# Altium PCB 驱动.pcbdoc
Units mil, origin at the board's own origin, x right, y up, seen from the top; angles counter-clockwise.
Board outline 18951.26 x 3455 mil, 2 copper layers (Top Layer, Bottom Layer); 74 components, 198 nets, 542 pads, 63 vias.
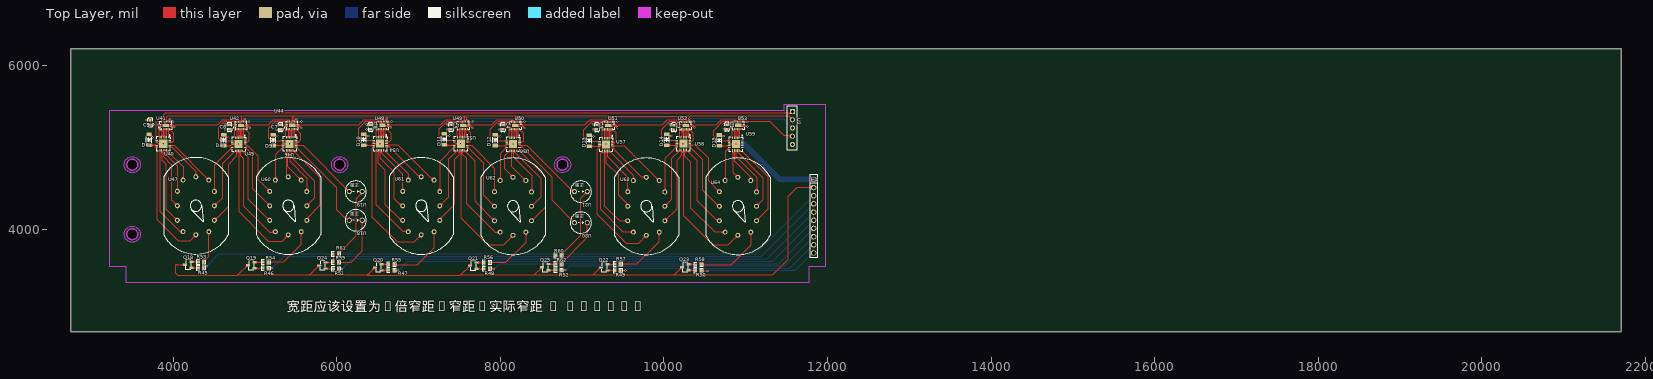
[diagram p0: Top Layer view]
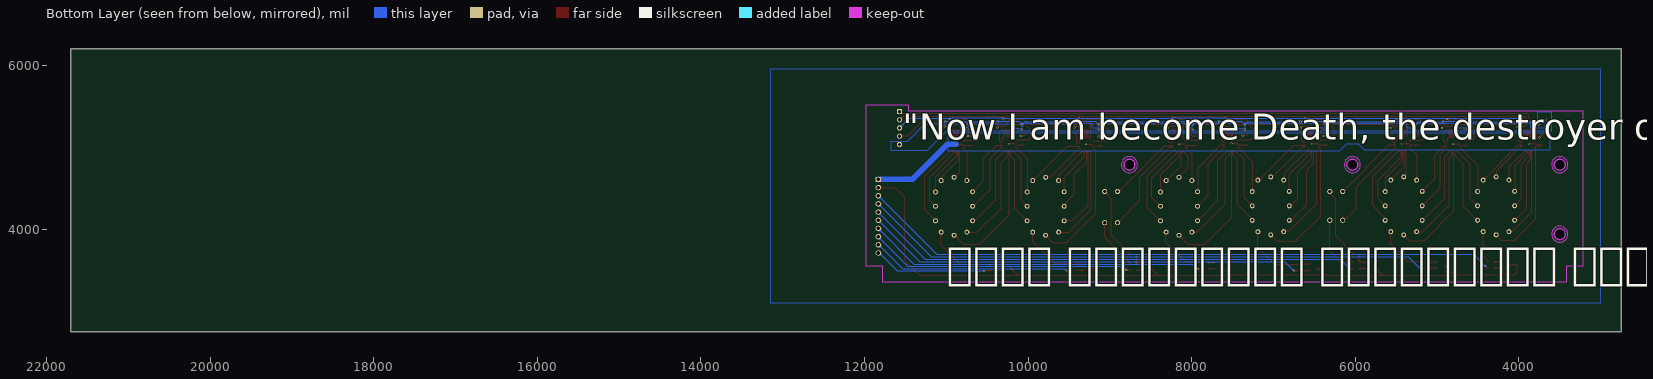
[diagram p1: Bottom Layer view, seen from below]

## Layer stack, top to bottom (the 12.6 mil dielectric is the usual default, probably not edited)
Top Layer: signal copper (thickness not stored)
Dielectric: dielectric 12.6, FR-4, Dk 4.8
Bottom Layer: signal copper (thickness not stored)

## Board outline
21701.26,2750 2750,2750 2750,6205 21701.26,6205
cut-out: 6101.93,4790 cw(c6035,4790) 5968.07,4790 cw(c6035,4790)
cut-out: 8826.93,4790 cw(c8760,4790) 8693.07,4790 cw(c8760,4790)
cut-out: 3566.93,3940 cw(c3500,3940) 3433.07,3940 cw(c3500,3940)
cut-out: 3566.93,4790 cw(c3500,4790) 3433.07,4790 cw(c3500,4790)

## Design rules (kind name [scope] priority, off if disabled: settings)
BoardOutlineClearance copperThickness1oz [All] p0: genericclearance=10 ignorepadtopadclearanceinfootprint=FALSE except(0: Arc-SplitContinuation Track-SplitContinuation SMDPad-SplitContinuation THPad-SplitContinuation Via-SplitContinuation Fill-SplitContinuation Poly-SplitContinuation Region-SplitContinuation Text-SplitContinuation; 6: SMDPad-CutoutEdge THPad-CutoutEdge Via-CutoutEdge Fill-CutoutEdge Region-CutoutEdge; 11.8: Track-OutlineEdge SMDPad-OutlineEdge THPad-OutlineEdge Via-OutlineEdge Fill-OutlineEdge Region-OutlineEdge Poly-OutlineEdge Text-OutlineEdge Track-CutoutEdge)
BoardOutlineClearance copperThickness2oz [All] p0: genericclearance=10 ignorepadtopadclearanceinfootprint=FALSE except(0: Arc-SplitContinuation Track-SplitContinuation SMDPad-SplitContinuation THPad-SplitContinuation Via-SplitContinuation Fill-SplitContinuation Poly-SplitContinuation Region-SplitContinuation Text-SplitContinuation; 6: SMDPad-CutoutEdge THPad-CutoutEdge Via-CutoutEdge Fill-CutoutEdge Region-CutoutEdge; 11.8: Track-OutlineEdge SMDPad-OutlineEdge THPad-OutlineEdge Via-OutlineEdge Fill-OutlineEdge Region-OutlineEdge Poly-OutlineEdge Text-OutlineEdge Track-CutoutEdge)
Clearance copperThickness1oz [(InNet('SWITCH1') OR InNet('SWITCH2') OR InNet('+5V') OR InNet('COLON1') OR InNet('SWITCH3') OR InNet('SWITCH6') OR InNet('SWITCH4') OR InNet('COLON2') OR InNet('A2') OR InNet('A3') OR InNet('A4') OR InNet('A5') OR InNet('A6') OR InNet('A7') OR InNet('GND') OR InNet('CLK') OR InNet('CS') OR InNet('MOSI') OR InNet('ADOT') OR InNet('A1') OR InNet('NIX_A7') OR InNet('NIX_A6') OR InNet('170V') OR InNet('170_GND') OR InNet('SWITCH5') OR InNet('NIX_D1') OR InNet('D_HV') OR InNet('NIX_G1') OR InNet('F7') OR InNet('F8') OR InNet('F9') OR InNet('F0') OR InNet('F5') OR InNet('F6') OR InNet('E0') OR InNet('FDOT') OR InNet('F1') OR InNet('F2') OR InNet('F3') OR InNet('F4') OR InNet('E8') OR InNet('E9') OR InNet('C2') OR InNet('C3') OR InNet('C4') OR InNet('C5') OR InNet('C6') OR InNet('C7') OR InNet('CDOT') OR InNet('C1') OR InNet('NIX_A0') OR InNet('NIX_B1') OR InNet('NIX_B2') OR InNet('NIX_B3') OR InNet('NIX_B4') OR InNet('NIX_B5') OR InNet('NIX_B7') OR InNet('NIX_B8') OR InNet('NIX_B9') OR InNet('NIX_B0') OR InNet('NIX_ADOT') OR InNet('NIX_A4') OR InNet('NIX_A2') OR InNet('NIX_A3') OR InNet('NIX_A1') OR InNet('NIX_A5') OR InNet('A_HV') OR InNet('NIX_A8') OR InNet('NIX_A9') OR InNet('C_HV') OR InNet('A8') OR InNet('C8') OR InNet('D5') OR InNet('EDOT') OR InNet('NIX_BDOT') OR InNet('NIX_E8') OR InNet('NIX_E0') OR InNet('NIX_E9') OR InNet('NIX_G0') OR InNet('E_HV') OR InNet('NIX_H0') OR InNet('F_HV') OR InNet('NIX_F4') OR InNet('NIX_F2') OR InNet('NIX_F3') OR InNet('NIX_F1') OR InNet('NIX_F5') OR InNet('NIX_FDOT') OR InNet('NIX_F6') OR InNet('NIX_F7') OR InNet('NIX_F0') OR InNet('NIX_F8') OR InNet('NIX_F9') OR InNet('C0') OR InNet('DDOT') OR InNet('D1') OR InNet('D2') OR InNet('D3') OR InNet('D4') OR InNet('C9') OR InNet('D7') OR InNet('D8') OR InNet('D9') OR InNet('D0') OR InNet('H0') OR InNet('H1') OR InNet('D6') OR InNet('E2') OR InNet('E3') OR InNet('E4') OR InNet('E5') OR InNet('E6') OR InNet('E7') OR InNet('E1') OR InNet('NIX_D4') OR InNet('NIX_D2') OR InNet('NIX_D3') OR InNet('NIX_D5') OR InNet('NIX_DDOT') OR InNet('NIX_D6') OR InNet('NIX_D7') OR InNet('NIX_D0') OR InNet('NIX_D8') OR InNet('NIX_D9') OR InNet('NIX_E4') OR InNet('NIX_E2') OR InNet('NIX_E3') OR InNet('NIX_E1') OR InNet('NIX_E5') OR InNet('NIX_EDOT') OR InNet('NIX_E6') OR InNet('NIX_E7') OR InNet('NIX_H1') OR InNet('B_HV') OR InNet('B4') OR InNet('G1') OR InNet('NIX_B6') OR InNet('NIX_CDOT') OR InNet('NIX_C4') OR InNet('NIX_C1') OR InNet('NIX_C3') OR InNet('NIX_C2') OR InNet('NIX_C5') OR InNet('NIX_C6') OR InNet('NIX_C7') OR InNet('NIX_C0') OR InNet('NIX_C8') OR InNet('NIX_C9') OR InNet('B0') OR InNet('B9') OR InNet('B8') OR InNet('B7') OR InNet('B6') OR InNet('B5') OR InNet('G0') OR InNet('B2') OR InNet('B1') OR InNet('BDOT') OR InNet('A0') OR InNet('A9') OR InNet('B3') OR InNet('$1N13403') OR InNet('$1N13394') OR InNet('$1N13396') OR InNet('$1N13344') OR InNet('$1N13352') OR InNet('$1N13345') OR InNet('$1N13353') OR InNet('$1N13346') OR InNet('$1N13354') OR InNet('$1N13347') OR InNet('$1N13355') OR InNet('$1N13348') OR InNet('$1N13359') OR InNet('$1N13349') OR InNet('$1N13358') OR InNet('$1N13350') OR InNet('$1N13351') OR InNet('$1N13978') OR InNet('$1N13404') OR InNet('$1N13405') OR InNet('$1N13979') OR InNet('$1N13980') OR InNet('$1N13981') OR InNet('$1N13982') OR InNet('$1N13983') OR InNet('$1N13668') OR InNet('$1N13669') OR InNet('$1N13670') OR InNet('$1N13767') OR InNet('$1N13768') OR InNet('$1N13769') OR InNet('G_HV1') OR InNet('G_HV2') OR InNet('H_HV1') OR InNet('H_HV2') OR InNet('$1N24687') OR InNet('$1N24696'))] p1: gap=7 ignorepadtopadclearanceinfootprint=FALSE except(4: Track-Track; 6: Track-SMDPad SMDPad-SMDPad Track-THPad SMDPad-THPad THPad-THPad Track-Via SMDPad-Via THPad-Via Via-Via Track-Fill SMDPad-Fill THPad-Fill Via-Fill Fill-Fill SMDPad-Region THPad-Region Via-Region Fill-Region Region-Region Track-Poly SMDPad-Poly THPad-Poly Via-Poly Fill-Poly Poly-Poly Track-Text SMDPad-Text THPad-Text Via-Text Fill-Text Region-Text Poly-Text Text-Text Track-Hole SMDPad-Hole THPad-Hole Via-Hole Fill-Hole Region-Hole Poly-Hole Text-Hole; 11.8: Track-Region Region-Poly Track-Sheet SMDPad-Sheet THPad-Sheet Via-Sheet Fill-Sheet Region-Sheet Poly-Sheet Text-Sheet Sheet-Hole)
Clearance copperThickness2oz [All] p1: gap=7 ignorepadtopadclearanceinfootprint=FALSE except(6: Track-SMDPad SMDPad-SMDPad Track-THPad SMDPad-THPad THPad-THPad Track-Via SMDPad-Via THPad-Via Via-Via Track-Fill SMDPad-Fill THPad-Fill Via-Fill Fill-Fill SMDPad-Region THPad-Region Via-Region Fill-Region Region-Region Track-Poly SMDPad-Poly THPad-Poly Via-Poly Fill-Poly Poly-Poly Track-Text SMDPad-Text THPad-Text Via-Text Fill-Text Region-Text Poly-Text Text-Text Track-Hole SMDPad-Hole THPad-Hole Via-Hole Fill-Hole Region-Hole Poly-Hole Text-Hole; 8: Track-Track; 11.8: Track-Region Region-Poly Track-Sheet SMDPad-Sheet THPad-Sheet Via-Sheet Fill-Sheet Region-Sheet Poly-Sheet Text-Sheet Sheet-Hole)
DiffPairsRouting differentialPair [All] p1: maxuncoupledlength=10 minlimit=6 maxlimit=6 mostfreqgap=6 toplayer_minwidth=5 toplayer_prefwidth=10 toplayer_maxwidth=100 bottomlayer_minwidth=5 bottomlayer_prefwidth=10 bottomlayer_maxwidth=100
PasteMaskExpansion pasteMaskExpansion [All] p1: expansion=0
PlaneConnect innerPlane [All] p1: planeconnectstyle=Relief reliefexpansion=20 reliefentries=4 reliefconductorwidth=10 reliefairgap=10
PolygonConnect copperRegion [All] p1: connectstyle=Relief reliefentries=4 reliefconductorwidth=10 polygonreliefangle="90 Angle" airgapwidth=10
RoutingVias viaSize [All] p1: viastyle="Through Hole" holewidth=12.0078 minholewidth=11.811 maxholewidth=248.0314 width=24.0158 minwidth=19.685 maxwidth=393.7008
SolderMaskExpansion solderMaskExpansion [All] p1: useseparateexpansions=TRUE expansion=2 expansionbottom=2
Width copperThickness1oz [All] p1: maxlimit=100 minlimit=5 preferedwidth=10
Width copperThickness2oz [All] p1: maxlimit=100 minlimit=8 preferedwidth=10

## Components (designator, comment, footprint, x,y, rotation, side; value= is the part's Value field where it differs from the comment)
C1 "CAP_0603" c0603 10770.07,5250.97 r270 top
C2 "CAP_0603" c0603 10119.85,5245.2 r270 top
C3 "CAP_0603" c0603 9179.1,5248.31 r270 top
C4 "CAP_0603" c0603 8032.13,5248.63 r270 top
C5 "CAP_0603" c0603 7394.85,5248.63 r270 top
C6 "CAP_0603" c0603 6414.85,5249.57 r270 top
C7 "CAP_0603" c0603 5313.07,5247.52 r270 top
C8 "CAP_0603" c0603 4688.12,5248.72 r270 top
C9 "CAP_0603" c0603 3720.6,5307.64 r90 top
D6 "ZMM51" LL-34_L3.5-W1.5-RD 3704.85,5092.87 r90 top
D8 "ZMM51" LL-34_L3.5-W1.5-RD 4619.85,5090.63 r90 top
D9 "ZMM51" LL-34_L3.5-W1.5-RD 5224.85,5090.63 r90 top
D10 "ZMM51" LL-34_L3.5-W1.5-RD 6331.27,5095.63 r90 top
D11 "ZMM51" LL-34_L3.5-W1.5-RD 7314.85,5100.63 r90 top
D12 "ZMM51" LL-34_L3.5-W1.5-RD 7939.85,5090.63 r90 top
D13 "ZMM51" LL-34_L3.5-W1.5-RD 9084.85,5083.76 r90 top
D14 "ZMM51" LL-34_L3.5-W1.5-RD 10034.85,5095.63 r90 top
D15 "ZMM51" LL-34_L3.5-W1.5-RD 10674.85,5085.63 r90 top
H4 "MH254V-11-10-1196" HDR-TH_10P-P2.54-V-M 11830,4160 r270 top
Q18 "13001_C2904842" SOT-23-3_L2.9-W1.3-P1.90-LS2.4-BR 4184.85,3565.63 r0 top
Q19 "13001_C2904842" SOT-23-3_L2.9-W1.3-P1.90-LS2.4-BR 4954.85,3560.79 r0 top
Q20 "13001_C2904842" SOT-23-3_L2.9-W1.3-P1.90-LS2.4-BR 6509.85,3533.62 r0 top
Q21 "13001_C2904842" SOT-23-3_L2.9-W1.3-P1.90-LS2.4-BR 7669.85,3555.63 r0 top
Q22 "13001_C2904842" SOT-23-3_L2.9-W1.3-P1.90-LS2.4-BR 9269.85,3533.62 r0 top
Q23 "13001_C2904842" SOT-23-3_L2.9-W1.3-P1.90-LS2.4-BR 10260.63,3535.63 r0 top
Q24 "13001_C2904842" SOT-23-3_L2.9-W1.3-P1.90-LS2.4-BR 5825.65,3557.32 r0 top
Q25 "13001_C2904842" SOT-23-3_L2.9-W1.3-P1.90-LS2.4-BR 8549.85,3536.94 r0 top
R45 "Res_0603" r0603 4339.91,3525.63 r180 top
R46 "Res_0603" r0603 5129.85,3523.23 r180 top
R47 "Res_0603" r0603 6665.65,3497.99 r180 top
R48 "Res_0603" r0603 7834.85,3517.68 r180 top
R49 "Res_0603" r0603 9432.89,3496.22 r180 top
R50 "Res_0603" r0603 10418.52,3497 r180 top
R51 "Res_0603" r0603 5989.46,3516.7 r180 top
R52 "Res_0603" r0603 8709.85,3499.54 r180 top
R53 "Res_0603" r0603 4339.91,3601.26 r180 top
R54 "Res_0603" r0603 5129.85,3600.59 r180 top
R55 "Res_0603" r0603 6665.65,3567.79 r180 top
R56 "Res_0603" r0603 7834.85,3593.94 r180 top
R57 "Res_0603" r0603 9432.89,3576.02 r180 top
R58 "Res_0603" r0603 10418.52,3565.63 r180 top
R59 "Res_0603" r0603 5989.08,3596.5 r180 top
R60 "Res_0603" r0603 8709.85,3575.26 r180 top
R61 "Res_0603" r0603 5989.08,3696.78 r180 top
R62 "Res_0603" r0603 8709.85,3680 r180 top
U2 "2.54mm1*5" 2.54mm1*5 11570,5237.72 r270 top
U18 "氖泡" 6*13氖泡 6232.84,4110.63 r180 top
U19 "氖泡" 6*13氖泡 6232.84,4460.63 r180 top
U20 "氖泡" 6*13氖泡 8984.85,4080.63 r180 top
U21 "氖泡" 6*13氖泡 8984.85,4460.63 r180 top
U40 "ULN2803A_C493377" QFN-20_L4.0-W4.0-P0.50-BL-EP 3879.18,5045.63 r180 top
U41 "74HC595BQ,115" DHVQFN-16_L3.5-W2.5-P0.50-BL-EP 3908.71,5269.69 r0 top
U42 "74HC595BQ,115" DHVQFN-16_L3.5-W2.5-P0.50-BL-EP 4829.85,5269.69 r0 top
U44 "74HC595BQ,115" DHVQFN-16_L3.5-W2.5-P0.50-BL-EP 5453.67,5270.24 r0 top
U45 "ULN2803A_C493377" QFN-20_L4.0-W4.0-P0.50-BL-EP 4800.32,5040.36 r180 top
U46 "ULN2803A_C493377" QFN-20_L4.0-W4.0-P0.50-BL-EP 5423.47,5044.69 r180 top
U47 "IN12" IN12 4278.65,4286.27 r0 top
U48 "74HC595BQ,115" DHVQFN-16_L3.5-W2.5-P0.50-BL-EP 6559.53,5270.63 r0 top
U49 "74HC595BQ,115" DHVQFN-16_L3.5-W2.5-P0.50-BL-EP 7546.96,5269.97 r0 top
U50 "74HC595BQ,115" DHVQFN-16_L3.5-W2.5-P0.50-BL-EP 8184.1,5269.3 r0 top
U51 "74HC595BQ,115" DHVQFN-16_L3.5-W2.5-P0.50-BL-EP 9320.95,5268.98 r0 top
U52 "74HC595BQ,115" DHVQFN-16_L3.5-W2.5-P0.50-BL-EP 10264.85,5268.98 r0 top
U53 "74HC595BQ,115" DHVQFN-16_L3.5-W2.5-P0.50-BL-EP 10909.85,5270.79 r0 top
U54 "ULN2803A_C493377" QFN-20_L4.0-W4.0-P0.50-BL-EP 6530,5046.06 r180 top
U55 "ULN2803A_C493377" QFN-20_L4.0-W4.0-P0.50-BL-EP 7517.43,5045.63 r180 top
U56 "ULN2803A_C493377" QFN-20_L4.0-W4.0-P0.50-BL-EP 8155.17,5040.63 r180 top
U57 "ULN2803A_C493377" QFN-20_L4.0-W4.0-P0.50-BL-EP 9290.76,5035.63 r180 top
U58 "ULN2803A_C493377" QFN-20_L4.0-W4.0-P0.50-BL-EP 10237.17,5047.42 r180 top
U59 "ULN2803A_C493377" QFN-20_L4.0-W4.0-P0.50-BL-EP 10879.66,5041.13 r180 top
U60 "IN12" IN12 5407.85,4285.63 r0 top
U61 "IN12" IN12 7032.73,4285.63 r0 top
U62 "IN12" IN12 8154.85,4280.63 r0 top
U63 "IN12" IN12 9784.85,4280.63 r0 top
U64 "IN12" IN12 10904.85,4280.63 r0 top

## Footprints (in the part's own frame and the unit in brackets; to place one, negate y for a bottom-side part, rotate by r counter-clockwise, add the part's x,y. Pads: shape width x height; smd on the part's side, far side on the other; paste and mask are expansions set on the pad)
2.54mm1*5 [mm]
  rect 1.6x1.6 hole 1: 1(-5.08,0)
  round 1.6 hole 1: 2(-2.54,0) 3(0,0) 4(2.54,0) 5(5.08,0)
  silkscreen extent -6.86,-1.52 6.86,1.4
6*13氖泡 [mm]
  round 1.6 hole 1: 1(-2,0) 2(2,0)
  silkscreen extent -3.3,-3.3 3.3,3.3
c0603 [mm]
  rect 0.8x0.9 smd: 1(-0.7,0) 2(0.7,0)
  silkscreen extent -1.41,-0.71 1.39,0.72
DHVQFN-16_L3.5-W2.5-P0.50-BL-EP [mm]
  rect 0.665x0.28 smd: 1(-1.658,-0.25) 8(1.658,-0.25) 9(1.658,0.25) 16(-1.658,0.25)
  rect 0.28x0.665 smd: 2(-1.25,-1.157) 3(-0.75,-1.157) 4(-0.25,-1.157) 5(0.25,-1.157) 6(0.75,-1.157) 7(1.25,-1.157) 10(1.25,1.157) 11(0.75,1.157) 12(0.25,1.157) 13(-0.25,1.157) 14(-0.75,1.157) 15(-1.25,1.157)
  rect 2x1 smd: 17(0,0)
  silkscreen extent -2.36,-1.33 1.83,1.33
HDR-TH_10P-P2.54-V-M [mm]
  rect 1.575x1.7 hole 1.1: 1(-11.43,0)
  round 1.7 hole 1.1: 2(-8.89,0) 3(-6.35,0) 4(-3.81,0) 5(-1.27,0) 6(1.27,0) 7(3.81,0) 8(6.35,0) 9(8.89,0) 10(11.43,0)
  silkscreen extent -12.9,-1.27 12.95,1.27
IN12 [mil]
  round 60 hole 31.5: 0(226.4,-177.2) 1(-157.5,-315) 2(-226.4,-177.2) 3(-226.4,0) 4(-226.4,177.2) 5(-157.5,315) 6(0,354.3) 7(157.5,315) 8(226.4,175) 9(226.4,0) DOT(0,-354.3) HV(157.5,-315)
  silkscreen extent -394,-591 394,591
LL-34_L3.5-W1.5-RD [mm]
  rect 1.1x1.7 smd: 1(-1.7,0) 2(1.7,0)
  silkscreen extent -0.9,-0.8 0.9,0.8
QFN-20_L4.0-W4.0-P0.50-BL-EP [mm]
  rect 0.28x0.8 smd: 1(-1,-2) 2(-0.5,-2) 3(0,-2) 4(0.5,-2) 5(1,-2) 11(1,2) 12(0.5,2) 13(0,2) 14(-0.5,2) 15(-1,2)
  rect 0.8x0.28 smd: 6(2,-1) 7(2,-0.5) 8(2,0) 9(2,0.5) 10(2,1) 16(-2,1) 17(-2,0.5) 18(-2,0) 19(-2,-0.5) 20(-2,-1)
  rect 2.5x2.5 smd: 21(0,0)
  silkscreen extent -2.15,-2.82 2.15,2.15
r0603 [mil]
  rect 31.75x34.02 smd: 1(-29.66,0) 2(29.66,0)
  silkscreen extent -55,-26 55,26
SOT-23-3_L2.9-W1.3-P1.90-LS2.4-BR [mm]
  rect 1.25x0.7 smd: 1(1,-0.95) 2(1,0.95) 3(-1,0)
  silkscreen extent -0.73,-1.53 0.73,1.53

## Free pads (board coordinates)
  round 19.68 hole 12.01: 22(3879.18,5045) 22(4800.32,5040) 22(5423.47,5045) 22(6530,5045) 22(7513.11,5050) 22(8154.57,5040) 22(9291.42,5040) 22(10235.32,5045) 22(10880.32,5040)

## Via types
v1: diameter 24.02, hole 12.01, Top Layer to Bottom Layer, 63 vias

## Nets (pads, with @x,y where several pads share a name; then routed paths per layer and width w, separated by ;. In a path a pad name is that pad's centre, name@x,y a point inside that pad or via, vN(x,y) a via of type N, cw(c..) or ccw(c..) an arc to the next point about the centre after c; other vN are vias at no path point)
170_GND: D6.2 D8.2 D9.2 D10.2 D11.2 D12.2 D13.2 D14.2 D15.2 H4.1 pad.22 U40.8 U40.21 U45.8 U45.21 U46.8 U46.21 U54.8 U54.21 U55.8 U55.21 U56.8 U56.21 U57.8 U57.21 U58.8 U58.21 U59.8 U59.21 | length 2451
  Top Layer w10: U40.8 U40.21 ; U45.8 U45.21 ; U46.8 U46.21 ; U54.8 U54.21 ; U55.8 U55.21 ; U56.8 U56.21 ; U57.8 U57.21 ; U58.8 U58.21 ; U59.8 10802.05,5040 pad.22@10880,5040
  Top Layer w20: D6.2 3709.62,5159.8 v1(3749.9,5119.53) ; D8.2 4652.41,5125 v1(4680,5125) ; D9.2 5247.41,5135 v1(5285,5135) ; D10.2 6353.83,5140 v1(6390,5140) ; D11.2 7337.41,5145 v1(7380,5145) ; D12.2 7962.41,5135 v1(8005,5135) ; D13.2 9100.54,5135 v1(9140,5135) ; D14.2 10057.41,5140 v1(10090,5140) ; D15.2 10687.41,5140 v1(10735,5140)
  Bottom Layer w70: pad.22@10880,5040 10985,5040 11415,4610 H4.1
170V: H4.2 Q18.3 Q19.3 Q20.3 Q21.3 Q22.3 Q23.3 Q24.3 Q25.3 | length 10015.3
  Top Layer w10: 4024.85,3565.63 Q18.3 ; 4785.57,3435.63 Q19.3@4910.48,3560.54 ; 5664.59,3435.63 Q24.3 ; 6375.82,3435.63 7510.48,3435.63 ; Q21.3 7510.48,3435.63 ; Q25.3 8409.18,3435.63 ; Q22.3 9132.5,3435.63 ; Q23.3 10121.26,3435.63 9132.5,3435.63 ; 7510.48,3435.63 8409.18,3435.63 ; 8409.18,3435.63 9132.5,3435.63
  Top Layer w15: 4024.85,3565.63 4024.85,3466.99 4056.2,3435.63 4785.57,3435.63 5664.59,3435.63 6375.82,3435.63 6375.82,3438.96 Q20.3 ; 10121.26,3435.63 11325.63,3435.63 11515,3625 11515,4400 11625,4510 H4.2
$1N13344: Q18.1 R45.2 | length 87.1
  Top Layer w10: Q18.1 4226.82,3525.63 R45.2
$1N13345: Q19.1 R46.2 | length 106
  Top Layer w10: Q19.1 5100.03,3523.39 R46.2
$1N13346: Q20.1 R47.2 | length 87.5
  Top Layer w10: Q20.1 6634.22,3496.22 R47.2
$1N13347: Q21.1 R48.2 | length 96.2
  Top Layer w10: Q21.1 7804.64,3518.23 R48.2
$1N13348: Q22.1 R49.2 | length 95
  Top Layer w10: Q22.1 9383.78,3496.22 9385,3495 9402.02,3495 R49.2
$1N13349: Q23.1 R50.2 | length 89.4
  Top Layer w10: Q23.1 10387.63,3498.23 R50.2
$1N13350: Q24.1 R51.2 | length 96.1
  Top Layer w10: Q24.1 5956.57,3519.92 R51.2
$1N13351: Q25.1 R52.2 | length 91
  Top Layer w10: Q25.1 R52.2
$1N13352: Q18.2 R53.2 | length 86.8
  Top Layer w10: Q18.2 4225.99,3601.26 R53.2
$1N13353: Q19.2 R54.2 | length 107
  Top Layer w10: Q19.2 5097.79,3598.19 R54.2
$1N13354: Q20.2 R55.2 | length 88.1
  Top Layer w10: Q20.2 6632.76,3571.02 R55.2
$1N13355: Q21.2 R56.2 | length 96.3
  Top Layer w10: Q21.2 7804.29,3593.03 R56.2
$1N13358: Q23.2 R58.2 | length 91.9
  Top Layer w10: Q23.2 10381.46,3573.03 R58.2
$1N13359: Q22.2 R57.2 | length 96.1
  Top Layer w10: Q22.2 9398.23,3571.02 R57.2
$1N13394: U41.9 U42.14 | length 874.2
  Top Layer w8: U41.9@3979.44,5280 4544.22,5280 4604.85,5340.63 4796.62,5340.63 4800.32,5336.93 U42.14@4800.32,5310.26
$1N13396: U42.9 U44.14 | length 575.4
  Top Layer w8: U42.9@4900.58,5280 5164.22,5280 5224.85,5340.63 5418.89,5340.63 5424.14,5335.38 U44.14@5424.14,5310.81
$1N13403: D6.1 U40.9 | length 98.8
  Top Layer w10: D6.1@3704.85,5023.7 D6.1@3707.09,5025.94 ; D6.1 D6.1@3707.09,5025.94 ; U40.9 D6.1@3707.09,5025.94
$1N13404: D8.1 U45.9 | length 103
  Top Layer w10: D8.1 4622.89,5020.67 U45.9
$1N13405: D9.1 U46.9 | length 120.4
  Top Layer w10: D9.1 5226.15,5025 U46.9
$1N13668: D10.1 U54.9 | length 121
  Top Layer w10: D10.1 6333.61,5026.37 U54.9
$1N13669: D11.1 U55.9 | length 127.1
  Top Layer w10: D11.1 7322.61,5025.94 U55.9
$1N13670: D12.1 U56.9 | length 137.7
  Top Layer w10: D12.1 7942.61,5020.94 U56.9
$1N13767: D13.1 U57.9 | length 127.5
  Top Layer w10: D13.1 9211.13,5016.83 U57.9
$1N13768: D14.1 U58.9 | length 124
  Top Layer w10: D14.1 10157.46,5028.7 U58.9
$1N13769: D15.1 U59.9 | length 127.2
  Top Layer w10: D15.1 10677.59,5021.44 U59.9
$1N13978: U44.9 U48.14 | length 1057.7
  Top Layer w8: U44.9@5523.85,5280 6269.22,5280 6329.85,5340.63 6524.85,5340.63 6529.85,5335.63 6529.85,5311.36 U48.14@6530,5311.2
$1N13979: U48.9 U49.14 | length 940.5
  Top Layer w8: U48.9@6629.32,5280 7269.22,5280 7329.85,5340.63 7512.53,5340.63 7517.43,5335.74 U49.14@7517.43,5310.54
$1N13980: U49.9 U50.14 | length 590.7
  Top Layer w8: U49.9@7617.42,5280 7894.22,5280 7954.85,5340.63 8150.21,5340.63 8154.85,5335.99 8154.85,5310.15 U50.14@8154.57,5309.87
$1N13981: U50.9 U51.14 | length 1089.9
  Top Layer w8: U50.9@8255.22,5280 9034.22,5280 9094.85,5340.63 9287.2,5340.63 9291.42,5336.41 U51.14@9291.42,5309.55
$1N13982: U51.9 U52.14 | length 895.9
  Top Layer w8: U51.9@9392.4,5280 9979.22,5280 10039.85,5340.63 10229.85,5340.63 10235.32,5335.16 U52.14@10235.32,5309.55
$1N13983: U52.9 U53.14 | length 594.6
  Top Layer w8: U52.9@10336.29,5280 10639.22,5280 10699.85,5340.63 10873.74,5340.63 10880.32,5334.05 U53.14@10880.32,5311.36
$1N24687: Q24.2 R59.2 R61.2 | length 195.4
  Top Layer w10: Q24.2 5957.65,3594.72 R59.2 R61.2
$1N24696: Q25.2 R60.2 R62.2 | length 196.1
  Top Layer w10: Q25.2 8679.27,3574.34 R60.2 R62.2
+5V: C1.1 C2.1 C3.1 C4.1 C5.1 C6.1 C7.1 C8.1 C9.1 U2.4 U41.10 U41.16 U42.10 U42.16 U44.10 U44.16 U48.10 U48.16 U49.10 U49.16 U50.10 U50.16 U51.10 U51.16 U52.10 U52.16 U53.10 U53.16 | length 9739.2
  Top Layer w10: C9.1 3759.92,5280.08 v1(3760,5280) ; v1(3814.85,5280.63) 3842.34,5280.63 U41.16 ; U41.10 3999.47,5315.26 v1(3999.85,5315.63) ; v1(4635,5280) 4635.47,5279.53 U42.16 ; U42.10 v1(4927.39,5315.26) ; v1(5265,5280) 5265.08,5280.08 U44.16 ; U44.10 v1(5569.85,5315.81) ; v1(6365,5280) 6365.47,5280.47 U48.16 ; U48.10 v1(6669.85,5316.2) ; v1(7350,5280) 7350.19,5279.81 U49.16 ; U49.10 v1(7664.85,5315.54) ; v1(7985,5280) 7985.86,5279.14 U50.16 ; U50.10 v1(8294.85,5314.87) ; v1(9135,5280) 9136.18,5278.82 U51.16 ; U51.10 v1(9434.85,5314.55) ; v1(10075,5280) 10076.18,5278.82 U52.16 ; U52.10 v1(10369.85,5314.55) ; v1(10725,5280) 10725.63,5280.63 U53.16 ; U53.10 v1(11014.85,5316.36)
  Top Layer w15: v1(11014.85,5316.36) 11298.64,5316.36 11472.28,5142.72 U2.4@11570,5142.72
  Bottom Layer w15: v1(3760,5280) 3760.63,5280.63 v1(3814.85,5280.63) 3849.85,5315.63 v1(3999.85,5315.63) 4599.37,5315.63 v1(4635,5280) 4670.26,5315.26 v1(4927.39,5315.26) 5229.74,5315.26 v1(5265,5280) 5300.81,5315.81 v1(5569.85,5315.81) 6329.19,5315.81 v1(6365,5280) 6401.2,5316.2 v1(6669.85,5316.2) 7313.8,5316.2 v1(7350,5280) 7385.54,5315.54 v1(7664.85,5315.54) 7949.46,5315.54 v1(7985,5280) 8019.87,5314.87 v1(8294.85,5314.87) 9100.13,5314.87 v1(9135,5280) 9169.55,5314.55 v1(9434.85,5314.55) 10040.45,5314.55 v1(10075,5280) 10109.55,5314.55 v1(10369.85,5314.55) 10690.45,5314.55 v1(10725,5280) 10761.36,5316.36 v1(11014.85,5316.36)
A0: U42.2 U45.4 | length 105
  Top Layer w10: U45.4 U42.2
A1: U40.5 U41.1 | length 149.4
  Top Layer w10: U40.5 3839.81,5135.68 3824.85,5150.63 3824.85,5241.25 U41.1
A2: U40.4 U41.2 | length 99.7
  Top Layer w10: U40.4 U41.2
A3: U40.3 U41.3 | length 99.7
  Top Layer w10: U40.3 U41.3
A4: U40.2 U41.4 | length 99.7
  Top Layer w10: U40.2 U41.4
A5: U40.1 U41.5 | length 99.7
  Top Layer w10: U40.1 U41.5
A6: U40.20 U41.6 | length 148.9
  Top Layer w10: U41.6 3938.24,5132.25 3959.85,5110.63 3959.85,5086.94 U40.20
A7: U40.19 U41.7 | length 212.1
  Top Layer w10: U40.19 3989.53,5065.31 3999.85,5075.63 3999.85,5182.18 U41.7
A8: U42.15 U45.6 | length 576.2
  Top Layer w10: U45.6 4720.68,5080.63 4579.85,5080.63 4549.85,5110.63 4549.85,5240.63 4624.47,5315.26 U42.15
A9: U42.1 U45.5 | length 158.3
  Top Layer w10: U45.5 4756.39,5119.1 4744.85,5130.63 4744.85,5240.11 U42.1
A_HV: R53.1 U47.HV | length 397.6
  Top Layer w10: R53.1 4436.15,3667.84 U47.HV
ADOT: U40.6 U41.15 | length 308.7
  Top Layer w10: U40.6 3784.85,5100.59 3784.85,5310.77 3789.34,5315.26 U41.15
B0: U44.5 U46.1 | length 101.5
  Top Layer w10: U46.1 5463.51,5124.09 U44.5
B1: U42.4 U45.2 | length 105
  Top Layer w10: U45.2 U42.4
B2: U42.5 U45.1 | length 105
  Top Layer w10: U45.1 U42.5
B3: U42.6 U45.20 | length 152.5
  Top Layer w10: U42.6 4859.38,5121.1 4874.85,5105.63 4874.85,5083.94 U45.20
B4: U42.7 U45.19 | length 216.8
  Top Layer w10: U45.19 4879.66,5060.63 4904.85,5060.63 4924.85,5080.63 4924.85,5178.33 U42.7
B5: U44.15 U46.6 | length 589.9
  Top Layer w10: U46.6 5196.43,5084.06 5159.85,5120.63 5159.85,5230.63 5245.02,5315.81 U44.15
B6: U44.1 U46.5 | length 153
  Top Layer w10: U46.5 5379.85,5123.43 5369.85,5133.43 5369.85,5241.84 U44.1
B7: U44.2 U46.4 | length 101.5
  Top Layer w10: U46.4 5404.46,5124.1 U44.2
B8: U44.3 U46.3 | length 101.5
  Top Layer w10: U46.3 5424.14,5124.09 U44.3
B9: U44.4 U46.2 | length 101.5
  Top Layer w10: U46.2 5443.83,5124.1 U44.4
B_HV: R54.1 U60.HV | length 649.6
  Top Layer w10: R54.1 5349.81,3600.59 5564.85,3815.63 5564.85,3970.13 U60.HV
BDOT: U42.3 U45.3 | length 105
  Top Layer w10: U45.3 U42.3
C0: U49.2 U55.4 | length 100
  Top Layer w10: U55.4@7497.75,5124.38 U49.2
C1: U48.1 U54.5 | length 154
  Top Layer w10: U54.5 6484.85,5124.8 6474.85,5134.8 6474.85,5241.37 U48.1
C2: U48.2 U54.4 | length 100.3
  Top Layer w10: U54.4 U48.2
C3: U48.3 U54.3 | length 100.3
  Top Layer w10: U54.3 U48.3
C4: U48.4 U54.2 | length 100.3
  Top Layer w10: U54.2 U48.4
C5: U48.5 U54.1 | length 100.3
  Top Layer w10: U54.1 U48.5
C6: U48.6 U54.20 | length 148.7
  Top Layer w10: U48.6 6589.06,5136.42 6609.85,5115.63 6609.85,5086.53 U54.20
C7: U48.7 U54.19 | length 217.1
  Top Layer w10: U54.19 6608.84,5065.63 6634.85,5065.63 6659.85,5090.63 6659.85,5173.96 U48.7
C8: U49.15 U55.6 | length 590.8
  Top Layer w10: U55.6 7438.06,5085.63 7284.85,5085.63 7249.85,5120.63 7249.85,5220.63 7344.75,5315.54 U49.15
C9: U49.1 U55.5 | length 148.2
  Top Layer w10: U55.5 7464.85,5137.59 7464.85,5243.28 U49.1
C_HV: R55.1 U61.HV | length 775.8
  Top Layer w10: R55.1 6982.01,3567.79 7189.85,3775.63 7189.85,3970.26 U61.HV
CDOT: U48.15 U54.6 | length 591.9
  Top Layer w10: U54.6 6451.05,5085.63 6299.85,5085.63 6264.85,5120.63 6264.85,5230.63 6350.42,5316.2 U48.15
CLK: U2.3 U41.11 U42.11 U44.11 U48.11 U49.11 U50.11 U51.11 U52.11 U53.11 | length 8097.7
  Top Layer w8: U41.11 3938.24,5332.35 3955.89,5350 v1(3960,5350) ; U42.11 4859.38,5332.35 4877.03,5350 v1(4880,5350) ; U44.11 5483.2,5332.9 5500.3,5350 v1(5510,5350) ; U48.11 6589.06,5333.29 6610.77,5355 v1(6615,5355) ; U49.11 7576.49,5332.63 7595,5351.13 v1(7595,5355) ; U50.11 8213.63,5331.96 8236.67,5355 v1(8240,5355) ; U51.11 9350.48,5331.64 9373.84,5355 v1(9375,5355) ; U52.11 10294.38,5331.64 10315,5352.26 v1(10315,5355) ; U53.11 10939.38,5333.45 10955.93,5350 v1(10960,5350)
  Bottom Layer w8: v1(3960,5350) v1(4880,5350) v1(5510,5350) 5515,5355 v1(6615,5355) v1(7595,5355) v1(8240,5355) v1(9375,5355) v1(10315,5355) 10955,5355 v1(10960,5350) 11462.72,5350 U2.3@11570,5242.72
COLON1: H4.5 R51.1 | length 6098.9
  Top Layer w10: R51.1 6020.18,3515.63 v1(6064.85,3515.63)
  Bottom Layer w10: v1(6064.85,3515.63) 6184.22,3635 11255,3635 H4.5
COLON2: H4.8 R52.1 | length 3260.5
  Top Layer w10: R52.1 v1(8794.85,3499.54)
  Bottom Layer w10: v1(8794.85,3499.54) 8845.31,3550 11470,3550 H4.8
CS: U2.2 U41.12 U42.12 U44.12 U48.12 U49.12 U50.12 U51.12 U52.12 U53.12 | length 8213.7
  Top Layer w8: U41.12@3918.55,5320.26 3918.55,5369.33 3929.69,5380.47 5464.85,5380.47 ; U42.12 4839.69,5375.47 4839.85,5375.63 ; U44.12@5463.51,5320.81 5464.85,5322.15 5464.85,5380.47 ; U48.12@6569.37,5321.2 6569.37,5380.16 6569.69,5380.47 ; U49.12@7556.8,5320.54 7556.8,5380.63 ; U50.12@8193.94,5319.87 8193.94,5380.63 ; U51.12 9330.79,5379.69 9329.85,5380.63 ; U52.12@10274.69,5319.55 10274.69,5380.63 ; U53.12 10919.85,5316.52 10919.85,5380.63 ; U2.2@11570,5342.72 11532.09,5380.63 10919.85,5380.63 ; 5464.85,5380.47 6569.69,5380.47 ; 6569.69,5380.47 6569.85,5380.63 7556.8,5380.63 ; 7556.8,5380.63 8193.94,5380.63 ; 8193.94,5380.63 9329.85,5380.63 ; 9329.85,5380.63 10274.69,5380.63 ; 10274.69,5380.63 10919.85,5380.63
D0: U50.5 U56.1 | length 104.2
  Top Layer w10: U50.5 8193.94,5120.39 U56.1@8194.54,5119.8
D1: U49.4 U55.2 | length 100
  Top Layer w10: U55.2 U49.4
D2: U49.5 U55.1 | length 100
  Top Layer w10: U55.1 U49.5
D3: U49.6 U55.20 | length 147.5
  Top Layer w10: U49.6 7576.49,5133.51 7595,5115 7595,5086.18 U55.20
D4: U49.7 U55.19 | length 205.7
  Top Layer w10: U55.19 7596.49,5065 7620,5065 7635,5080 7635,5185.57 U49.7
D5: U50.15 U56.6 | length 636.3
  Top Layer w10: U56.6 7890.48,5080 7869.85,5100.63 7869.85,5215.63 7969.09,5314.87 U50.15
D6: U50.1 U56.5 | length 157.1
  Top Layer w10: U56.5@8115.8,5119.8 8110.69,5119.8 8099.85,5130.63 8099.85,5240.47 U50.1
D7: U50.2 U56.4 | length 104.2
  Top Layer w10: U50.2 8134.89,5120.38 U56.4@8135.48,5119.8
D8: U50.3 U56.3 | length 104.2
  Top Layer w10: U50.3 8154.57,5120.39 U56.3@8155.17,5119.8
D9: U50.4 U56.2 | length 104.2
  Top Layer w10: U50.4 8174.26,5120.38 U56.2@8174.85,5119.8
D_HV: R56.1 U62.HV | length 678.6
  Top Layer w10: R56.1 8068.15,3593.94 8314.85,3840.63 8314.85,3963.13 U62.HV
DDOT: U49.3 U55.3 | length 100
  Top Layer w10: U55.3 U49.3
E0: U52.2 U58.4 | length 98
  Top Layer w10: U52.2 10215.64,5128.01 U58.4
E1: U51.1 U57.5 | length 157
  Top Layer w10: U57.5 9249.85,5114.37 9239.85,5124.37 9239.85,5243.3 U51.1
E2: U51.2 U57.4 | length 109.3
  Top Layer w10: U57.4 9271.74,5115.05 U51.2
E3: U51.3 U57.3 | length 109.3
  Top Layer w10: U57.3 9291.42,5115.04 U51.3
E4: U51.4 U57.2 | length 109.3
  Top Layer w10: U57.2 9311.11,5115.05 U51.4
E5: U51.5 U57.1 | length 109.3
  Top Layer w10: U57.1 9330.79,5115.04 U51.5
E6: U51.6 U57.20 | length 156.6
  Top Layer w10: U51.6 9350.48,5125 9369.85,5105.63 9369.85,5075.35 U57.20
E7: U51.7 U57.19 | length 218.8
  Top Layer w10: U57.19 9399.53,5055.31 9409.85,5065.63 9409.85,5183.72 U51.7
E8: U52.15 U58.6 | length 595.3
  Top Layer w10: U58.6 10157.27,5085.63 9999.85,5085.63 9964.85,5120.63 9964.85,5215.63 10063.77,5314.55 U52.15
E9: U52.1 U58.5 | length 146.2
  Top Layer w10: U58.5 10194.85,5126.16 10184.85,5136.16 10184.85,5244.4 U52.1
E_HV: R57.1 U63.HV | length 710
  Top Layer w10: R57.1 9670.23,3576.02 9942.35,3848.13 U63.HV
EDOT: U51.15 U57.6 | length 614.8
  Top Layer w10: U57.6 9211.39,5075.63 9044.85,5075.63 9014.85,5105.63 9014.85,5210.63 9118.77,5314.55 U51.15
F0: U53.5 U59.1 | length 105.6
  Top Layer w10: U59.1 10919.69,5120.53 U53.5
F1: U52.4 U58.2 | length 98
  Top Layer w10: U52.4 10255.01,5128.01 U58.2
F2: U52.5 U58.1 | length 98
  Top Layer w10: U52.5 10276.54,5221.56 U58.1
F3: U52.6 U58.20 | length 145.5
  Top Layer w10: U52.6 10294.38,5141.1 10314.85,5120.63 10314.85,5087.86 U58.20
F4: U52.7 U58.19 | length 204.2
  Top Layer w10: U52.7 10354.85,5182.62 10354.85,5080.63 10341.32,5067.1 U58.19
F5: U53.15 U59.6 | length 612.3
  Top Layer w10: U59.6 10800.78,5080.63 10629.85,5080.63 10599.85,5110.63 10599.85,5200.63 10715.58,5316.36 U53.15
F6: U53.1 U59.5 | length 151.8
  Top Layer w10: U59.5 10839.85,5119.87 10829.85,5129.87 10829.85,5246.21 U53.1
F7: U53.2 U59.4 | length 105.6
  Top Layer w10: U59.4 10860.64,5120.54 U53.2
F8: U53.3 U59.3 | length 105.6
  Top Layer w10: U59.3 10880.32,5120.53 U53.3
F9: U53.4 U59.2 | length 105.6
  Top Layer w10: U59.2 10900.01,5120.54 U53.4
F_HV: R58.1 U64.HV | length 874.2
  Top Layer w10: R58.1 10819.85,3565.63 11064.85,3810.63 11064.85,3963.13 U64.HV
FDOT: U52.3 U58.3 | length 98
  Top Layer w10: U52.3 10235.32,5128.02 U58.3
G0: U44.6 U46.20 | length 150.7
  Top Layer w10: U44.6 5483.2,5137.29 5504.85,5115.63 5504.85,5086.7 U46.20
G1: U44.7 U46.19 | length 222
  Top Layer w10: U46.19 5533.59,5064.37 5554.85,5085.63 5554.85,5172.69 U44.7
G_HV1: R59.1 U18.1 | length 730.1
  Top Layer w10: R59.1 6175.71,3596.5 6314.85,3735.63 6314.85,4107.37 U18.1
G_HV2: R61.1 U19.1 | length 885.2
  Top Layer w10: R61.1 6240,3918.03 6240,4374.91 6311.58,4446.49 U19.1
GND: C1.2 C2.2 C3.2 C4.2 C5.2 C6.2 C7.2 C8.2 C9.2 U2.5 U41.8 U41.13 U41.17 U42.8 U42.13 U42.17 U44.8 U44.13 U44.17 U48.8 U48.13 U48.17 U49.8 U49.13 U49.17 U50.8 U50.13 U50.17 U51.8 U51.13 U51.17 U52.8 U52.13 U52.17 U53.8 U53.13 U53.17 | length 2018.7
  Top Layer w10: v1(3665,5335) 3665.2,5335.2 C9.2 ; U41.13 3898.87,5281.68 3920.7,5259.85 U41.8 4005.15,5259.85 v1(4015,5250) ; v1(4635,5220) 4686.95,5220 C8.2 ; U42.13 4820.01,5273.67 4833.83,5259.85 U42.8 4920.15,5259.85 v1(4940,5240) ; v1(5265,5215) 5308.1,5215 C7.2 ; U44.13 5443.83,5271.99 5455.42,5260.4 U44.8 5549.6,5260.4 v1(5570,5240) ; v1(6365,5220) 6412.84,5220 C6.2 ; U48.13 6549.69,5272.12 6561.02,5260.79 U48.8 6649.21,5260.79 v1(6665,5245) ; v1(7350,5220) 7393.78,5220 C5.2 ; U49.13 7537.12,5260.13 U49.8 7639.87,5260.13 v1(7660,5240) ; v1(7985,5220) 8031.06,5220 C4.2 ; U50.13 8174.26,5273.9 8188.7,5259.46 U50.8 8275.54,5259.46 v1(8295,5240) ; v1(9135,5220) 9135.75,5220.75 C3.2 ; U51.13 9311.11,5263.89 9315.86,5259.14 U51.8 9420.86,5259.14 v1(9435,5245) ; v1(10075,5220) 10117.49,5220 C2.2 ; U52.13 10255.01,5274.94 10270.82,5259.14 U52.8 10360.86,5259.14 v1(10375,5245) ; v1(10725,5225) 10768.48,5225 C1.2 ; U53.13 10900.01,5273.03 10912.09,5260.95 U53.8 11014.05,5260.95 v1(11020,5255)
H0: U50.6 U56.20 | length 152.5
  Top Layer w10: U50.6 8213.63,5136.85 8234.85,5115.63 8234.85,5081.37 U56.20@8233.91,5080.43
H1: U50.7 U56.19 | length 222.5
  Top Layer w10: U50.7 8279.85,5177.19 8279.85,5070.63 8269.85,5060.63 8234.01,5060.63 U56.19@8233.91,5060.74
H_HV1: R60.1 U20.1 | length 639.6
  Top Layer w10: R60.1 9063.59,3899.34 U20.1
H_HV2: R62.1 U21.1 | length 914.9
  Top Layer w10: R62.1 8985,3925.49 8985,4382.04 U21.1
MOSI: U2.1 U41.14 | length 7777.4
  Top Layer w8: U41.14@3879.18,5325.26 3879.18,5389.96 3904.85,5415.63 U2.1@11542.91,5415.63
  Top Layer w10: U2.1@11542.91,5415.63 U2.1@11570,5442.72
NIX_A0: U45.12 U47.0 | length 968.6
  Top Layer w10: U47.0 4508.29,4109.07 4679.85,4280.63 4679.85,4795.63 4780.63,4896.41 U45.12
NIX_A1: U40.11 U47.1 | length 1133.8
  Top Layer w10: U40.11 3839.81,4215.68 4084.22,3971.27 U47.1
NIX_A2: U40.12 U47.2 | length 937.7
  Top Layer w10: U40.12 3859.49,4851 3909.85,4800.63 3909.85,4251.47 U47.2
NIX_A3: U40.13 U47.3 | length 752.3
  Top Layer w10: U40.13 3879.18,4891.31 3979.85,4790.63 3979.85,4358.67 U47.3
NIX_A4: U40.14 U47.4 | length 567
  Top Layer w10: U40.14 3898.86,4926.63 4049.85,4775.63 4049.85,4465.87 U47.4
NIX_A5: U40.15 U47.5 | length 449.5
  Top Layer w10: U40.15 4121.15,4764.29 U47.5
NIX_A6: U40.16 U47.6 | length 514
  Top Layer w10: U40.16 3984.22,5006.26 4278.65,4711.83 U47.6
NIX_A7: U40.17 U47.7 | length 654.1
  Top Layer w10: U40.17 4011.48,5025.94 U47.7
NIX_A8: U45.10 U47.8 | length 629.4
  Top Layer w10: U47.8 4505.05,4784.46 U45.10
NIX_A9: U45.11 U47.9 | length 781.3
  Top Layer w10: U47.9 4599.85,4381.07 4599.85,4800.52 U45.11
NIX_ADOT: U40.10 U47.DOT | length 1501.4
  Top Layer w10: U40.10 3800.44,4120.05 4059.85,3860.63 4207.32,3860.63 U47.DOT
NIX_B0: U46.15 U60.0 | length 1061.6
  Top Layer w10: U46.15 5794.85,4633.94 5794.85,4290.63 5634.25,4130.03 U60.0
NIX_B1: U45.14 U60.1 | length 1217.6
  Top Layer w10: U45.14 4820,4905.48 4859.85,4865.63 4859.85,4285.63 5179.85,3965.63 5245.35,3965.63 U60.1
NIX_B2: U45.15 U60.2 | length 997.3
  Top Layer w10: U45.15 4914.85,4886.46 4914.85,4370.63 5177.05,4108.43 U60.2
NIX_B3: U45.16 U60.3 | length 840.6
  Top Layer w10: U45.16 4964.85,4915.2 4964.85,4502.23 U60.3
NIX_B4: U45.17 U60.4 | length 701.1
  Top Layer w10: U45.17 4909.82,5020.67 5034.85,4895.63 5034.85,4609.43 U60.4
NIX_B5: U46.10 U60.5 | length 443.8
  Top Layer w10: U60.5 5250.35,4910.94 U46.10
NIX_B6: U46.11 U60.6 | length 335.9
  Top Layer w10: U46.11 5384.1,4663.68 U60.6
NIX_B7: U46.12 U60.7 | length 432.2
  Top Layer w10: U46.12 5403.78,4762.2 U60.7
NIX_B8: U46.13 U60.8 | length 592.6
  Top Layer w10: U46.13 5423.47,4837.01 5634.25,4626.23 U60.8
NIX_B9: U46.14 U60.9 | length 834.5
  Top Layer w10: U46.14 5443.15,4877.33 5724.85,4595.63 5724.85,4376.23 U60.9
NIX_BDOT: U45.13 U60.DOT | length 1531.3
  Top Layer w10: U45.13 4800.32,4220.16 5164.85,3855.63 5332.15,3855.63 U60.DOT
NIX_C0: U55.12 U61.0 | length 957.3
  Top Layer w10: U61.0 7259.13,4122.58 7439.85,4303.3 7439.85,4855.63 7497.74,4913.53 U55.12
NIX_C1: U54.11 U61.1 | length 1207.4
  Top Layer w10: U54.11 6474.85,4951.53 6474.85,4305.63 6804.85,3975.63 6870.23,3975.63 U61.1
NIX_C2: U54.12 U61.2 | length 992.8
  Top Layer w10: U54.12 6510.31,4805.17 6594.85,4720.63 6594.85,4300.63 6787.05,4108.43 U61.2
NIX_C3: U54.13 U61.3 | length 805.8
  Top Layer w10: U54.13 6530,4870.48 6704.85,4695.63 6704.85,4370.63 6789.85,4285.63 U61.3
NIX_C4: U54.14 U61.4 | length 610.8
  Top Layer w10: U54.14 6549.68,4930.8 6806.33,4674.16 U61.4
NIX_C5: U54.15 U61.5 | length 501.7
  Top Layer w10: U54.15 6583.52,4967.32 6875.23,4675.6 U61.5
NIX_C6: U54.16 U61.6 | length 575.9
  Top Layer w10: U54.16 6643.8,5006.69 7010.55,4639.93 U61.6
NIX_C7: U54.17 U61.7 | length 757.8
  Top Layer w10: U54.17 6754.12,5026.37 7179.85,4600.63 U61.7
NIX_C8: U55.10 U61.8 | length 620
  Top Layer w10: U61.8 7259.13,4826.7 U55.10
NIX_C9: U55.11 U61.9 | length 772.4
  Top Layer w10: U61.9 7259.85,4285.63 7364.85,4390.63 7364.85,4853.68 U55.11
NIX_CDOT: U54.10 U61.DOT | length 1626.7
  Top Layer w10: U54.10 6429.85,4985.27 6429.85,4155.63 6739.85,3845.63 6947.03,3845.63 U61.DOT
NIX_D0: U56.15 U62.0 | length 1098.5
  Top Layer w10: U56.15@8194.54,4962.32 8233.17,4962.32 8549.85,4645.63 8549.85,4272.03 U62.0
NIX_D1: U55.14 U62.1 | length 1232.7
  Top Layer w10: U55.14 7537.11,4918.37 7589.85,4865.63 7589.85,4310.63 7939.85,3960.63 7992.35,3960.63 U62.1
NIX_D2: U55.15 U62.2 | length 1017.4
  Top Layer w10: U55.15 7684.85,4838.85 7684.85,4350.63 7928.45,4107.03 U62.2
NIX_D3: U55.16 U62.3 | length 863.3
  Top Layer w10: U55.16 7794.85,4807.59 7794.85,4414.23 U62.3
NIX_D4: U55.17 U62.4 | length 737
  Top Layer w10: U55.17 7649.54,5025.94 7928.45,4747.03 U62.4
NIX_D5: U56.10 U62.5 | length 438.8
  Top Layer w10: U62.5 7997.35,4922.61 U56.10@8076.43,5001.69
NIX_D6: U56.11 U62.6 | length 402.3
  Top Layer w10: U56.11@8115.8,4962.32 8044.85,4891.37 8044.85,4744.93 U62.6
NIX_D7: U56.12 U62.7 | length 439.9
  Top Layer w10: U56.12@8135.48,4962.32 8135.48,4772.51 U62.7
NIX_D8: U56.13 U62.8 | length 600.3
  Top Layer w10: U56.13@8155.17,4962.32 8155.17,4885.32 8381.25,4659.23 U62.8
NIX_D9: U56.14 U62.9 | length 861.3
  Top Layer w10: U56.14@8174.85,4962.32 8174.85,4940.64 8494.85,4620.63 8494.85,4394.23 U62.9
NIX_DDOT: U55.13 U62.DOT | length 1649.8
  Top Layer w10: U55.13 7517.43,4138.05 7844.85,3810.63 8039.15,3810.63 U62.DOT
NIX_E0: U58.12 U63.0 | length 950.7
  Top Layer w10: U63.0 10159.85,4252.03 10159.85,4845.63 10217.48,4903.27 U58.12
NIX_E1: U57.11 U63.1 | length 1240.7
  Top Layer w10: U57.11 9224.85,4930.35 9224.85,4245.63 9504.85,3965.63 U63.1
NIX_E2: U57.12 U63.2 | length 1031.9
  Top Layer w10: U57.12 9271.07,4289.41 9457.05,4103.43 U63.2
NIX_E3: U57.13 U63.3 | length 787.1
  Top Layer w10: U57.13 9290.76,4814.72 9439.85,4665.63 9439.85,4422.77 9558.45,4304.17 U63.3
NIX_E4: U57.14 U63.4 | length 601.8
  Top Layer w10: U57.14 9310.44,4885.04 9558.45,4637.03 U63.4
NIX_E5: U57.15 U63.5 | length 484.4
  Top Layer w10: U57.15 9627.35,4659.67 U63.5
NIX_E6: U57.16 U63.6 | length 565.2
  Top Layer w10: U57.16 9369.5,4995.98 9730.55,4634.93 U63.6
NIX_E7: U57.17 U63.7 | length 746.9
  Top Layer w10: U57.17 9519.54,5015.94 9939.85,4595.63 U63.7
NIX_E8: U58.10 U63.8 | length 613.4
  Top Layer w10: U63.8 10011.25,4860.87 U58.10
NIX_E9: U58.11 U63.9 | length 765.3
  Top Layer w10: U63.9 10089.85,4359.23 10089.85,4860.73 U58.11
NIX_EDOT: U57.10 U63.DOT | length 1612.7
  Top Layer w10: U57.10 9179.85,4964.09 9179.85,4190.63 9539.85,3830.63 9689.15,3830.63 U63.DOT
NIX_F0: U59.15 U64.0 | length 1081.6
  Top Layer w10: U59.15 10953.1,4962.39 11269.85,4645.63 11269.85,4242.03 U64.0
NIX_F1: U58.14 U64.1 | length 1285.1
  Top Layer w10: U58.14 10256.85,4893.63 10329.85,4820.63 10329.85,4255.63 10624.85,3960.63 10742.35,3960.63 U64.1
NIX_F2: U58.15 U64.2 | length 1047.2
  Top Layer w10: U58.15 10399.85,4845.38 10399.85,4355.63 10652.05,4103.43 U64.2
NIX_F3: U58.16 U64.3 | length 882.6
  Top Layer w10: U58.16 10469.85,4854.12 10469.85,4480.63 10669.85,4280.63 U64.3
NIX_F4: U58.17 U64.4 | length 759.2
  Top Layer w10: U58.17 10382.75,5027.73 10544.85,4865.63 10544.85,4591.43 U64.4
NIX_F5: U59.10 U64.5 | length 428.3
  Top Layer w10: U64.5 10747.35,4948.19 U59.10
NIX_F6: U59.11 U64.6 | length 354.2
  Top Layer w10: U59.11 10840.29,4699.5 U64.6
NIX_F7: U59.12 U64.7 | length 450.6
  Top Layer w10: U59.12 10859.97,4840.52 11062.35,4638.13 U64.7
NIX_F8: U59.13 U64.8 | length 614
  Top Layer w10: U59.13 10879.66,4890.83 11134.85,4635.63 11134.85,4459.23 U64.8
NIX_F9: U59.14 U64.9 | length 842.9
  Top Layer w10: U59.14 10899.34,4941.15 11209.85,4630.63 11209.85,4359.23 U64.9
NIX_FDOT: U58.13 U64.DOT | length 1664.1
  Top Layer w10: U58.13 10237.17,4168.31 10594.85,3810.63 10789.15,3810.63 U64.DOT
NIX_G0: U18.2 U46.16 | length 1178.9
  Top Layer w10: U46.16 5994.85,4512.68 5994.85,4245.63 6129.85,4110.63 U18.2
NIX_G1: U19.2 U46.17 | length 885.7
  Top Layer w10: U46.17 5589.74,5025 U19.2
NIX_H0: U20.2 U56.16 | length 1219.9
  Top Layer w10: U56.16@8233.91,5001.69 8268.8,5001.69 8634.85,4635.63 8634.85,4351.89 U20.2
NIX_H1: U21.2 U56.17 | length 904.5
  Top Layer w10: U56.17@8233.91,5021.37 8329.12,5021.37 8889.85,4460.63 U21.2
SWITCH1: H4.3 R45.1 | length 7826.7
  Top Layer w10: R45.1 4384.85,3525.63 v1(4409.85,3550.63)
  Bottom Layer w10: v1(4409.85,3550.63) 4554.22,3695 11115,3695 H4.3
SWITCH2: H4.4 R46.1 | length 6996.4
  Top Layer w10: R46.1 5207.45,3523.23 v1(5209.85,3525.63)
  Bottom Layer w10: v1(5209.85,3525.63) 5349.22,3665 11185,3665 H4.4
SWITCH3: H4.6 R47.1 | length 5390.1
  Top Layer w10: R47.1 6697.67,3495.63 v1(6749.85,3495.63)
  Bottom Layer w10: v1(6749.85,3495.63) 6859.22,3605 11325,3605 H4.6
SWITCH4: H4.7 R48.1 | length 4171.1
  Top Layer w10: R48.1 7866.56,3515.63 v1(7924.85,3515.63)
  Bottom Layer w10: v1(7924.85,3515.63) 7984.22,3575 11395,3575 H4.7
SWITCH5: H4.9 R49.1 | length 2495.7
  Top Layer w10: R49.1 v1(9529.85,3496.22)
  Bottom Layer w10: v1(9529.85,3496.22) 9530.19,3496.22 9553.97,3520 11530,3520 11810.43,3800.43 11824.57,3800.43 H4.9@11830,3795
SWITCH6: H4.10 R50.1 | length 1468.8
  Top Layer w10: R50.1 10455.18,3490 v1(10530,3490)
  Bottom Layer w10: v1@10535,3495 11600.86,3495 11805.86,3700 11820,3700 H4.10
pads on no net: U40.7 U40.18 U45.7 U45.18 U46.7 U46.18 U53.6 U53.7 U53.9 U54.7 U54.18 U55.7 U55.18 U56.7 U56.18 U57.7 U57.18 U58.7 U58.18 U59.7 U59.16 U59.17 U59.18 U59.19 U59.20

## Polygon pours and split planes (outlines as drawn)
GND on Bottom Layer (solid, remove dead copper, pour order 2): 3000,5955 13150,5955 13150,3100 3000,3100
170_GND on Bottom Layer (solid, remove dead copper, pour order 0): 3619.85,4965.63 5884.85,4965.63 5959.85,5040.63 6109.85,5040.63 6194.85,4955.63 10974.85,4955.63 10974.85,5175.63 10974.89,5180.63 3619.85,5180.63
GND on Bottom Layer (solid, remove dead copper, pour order 4): 11567.5,5076.96 11473.04,5076.96 11260,5290 10830.47,5290 10830.47,5246.83 10829.85,5246.21 10730,5246.21 10730,5292.86 10170.59,5292.86 10170.59,5235.59 10170,5235 10075,5235 10055,5275 10045,5293.36 9223.92,5293.36 9223.92,5239.99 9135,5239.99 9135,5293.36 8075.75,5293.36 8075.75,5240.99 7994.01,5240.99 7990,5245 7990,5293.36 7440,5293.36 7440,5237.5 7347.5,5237.5 7345,5240 7345,5293.86 6470,5293.86 6470,5243.15 6469.53,5242.68 6365.96,5242.68 6365.96,5294.86 5367.92,5294.86 5367.92,5242.92 5365,5240 5260,5240 5260,5295.36 4745,5295.36 4745,5240.26 4744.85,5240.11 4631.73,5240.11 4631.73,5293.27 4630,5295 3860,5295 3860,5240 3677.08,5240 3677.08,5310.32 3770,5310.32 3770,5435 3604.88,5435 3604.88,5199.12 11000,5199.12 11239.12,4960 11675,4960 11675,5070 11680,5075 11567.5,5075

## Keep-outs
Board Outline Layer:
  circle w1: c6035,4790 r66.93
  region: 6101.93,4790 cw(c6035,4790) 5968.07,4790 cw(c6035,4790)
  circle w1: c8760,4790 r66.93
  region: 8826.93,4790 cw(c8760,4790) 8693.07,4790 cw(c8760,4790)
  circle w1: c3500,3940 r66.93
  region: 3566.93,3940 cw(c3500,3940) 3433.07,3940 cw(c3500,3940)
  circle w1: c3500,4790 r66.93
  region: 3566.93,4790 cw(c3500,4790) 3433.07,4790 cw(c3500,4790)
  region: 3598.43,4790 cw(c3500,4790) 3401.57,4790 cw(c3500,4790)
  region: 3598.43,3940 cw(c3500,3940) 3401.57,3940 cw(c3500,3940)
  region: 6133.43,4790 cw(c6035,4790) 5936.57,4790 cw(c6035,4790)
  region: 8858.43,4790 cw(c8760,4790) 8661.57,4790 cw(c8760,4790)
  lines w10: 3219.85,3550.63 3219.85,5450.76 3421.56,5450.76 11465,5447.17 11465,5522.74 11979.85,5522.74 11979.85,3550.63 11776.46,3550.63 11776.46,3350.63 3419.85,3350.63 3419.85,3550.63 3219.85,3550.63

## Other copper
Top Layer:
  drawing of 579 lines, arcs and shapes, not listed
Bottom Layer:
  drawing of 79 lines, arcs and shapes, not listed

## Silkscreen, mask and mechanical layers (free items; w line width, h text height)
Top Silkscreen Layer:
  text "宽距应该设置为3倍窄距+窄距-实际窄距 = 700mil" at 5390,3000 h120
Bottom Silkscreen Layer:
  text "\"Now I am become Death, the destroyer of worlds.\"" at 11530,5095 h314.96
  text "श्री भगवानुवाच कालोऽस्मि लोकक्षयकृत्प्रवृद्धो" at 10995,3395 h393.7
Mechanical Layer:
  circle w1: c6035,4790 r66.93
  circle w1: c8760,4790 r66.93
  circle w1: c3500,3940 r66.93
  circle w1: c3500,4790 r66.93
